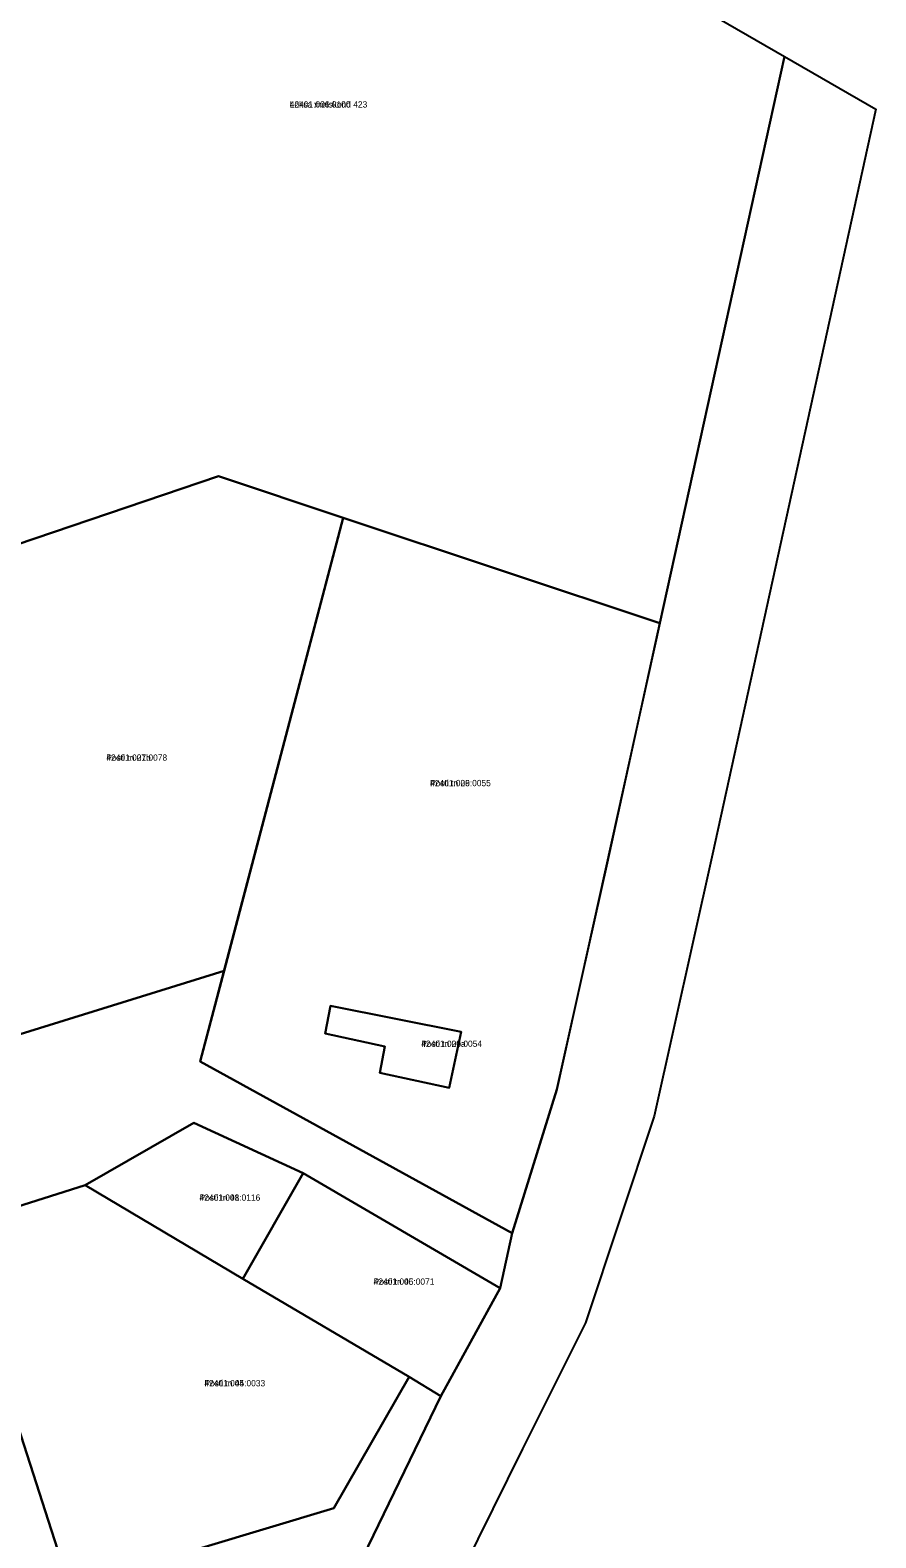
# Model space of a CAD drawing. Extents: x 595979 to 597983, y 6604231 to 6607350.
# Drawn here: x 597780.8 to 597982.6, y 6606558.1 to 6606917.7 of the extents above; entities that cross this region are included whole.
import ezdxf

# ---------------------------------------------------------------- set-up
doc = ezdxf.new("R2010")
doc.units = 0
for name, color, linetype in [('L_AADRESS', 7, 'Continuous'), ('PIIR', 7, 'Continuous'), ('TUNNUS', 7, 'Continuous')]:
    doc.layers.add(name, color=color, linetype=linetype)

msp = doc.modelspace()

# ---------------------------------------------------------------- linework, layer by layer
at = {"layer": 'PIIR'}
for points in [[(597960.77, 6606911.42), (597931.09, 6606776.25), (597855.49, 6606801.38), (597825.72, 6606811.32), (597742.46, 6606783.1), (597698.67, 6606769.19), (597711.53, 6606826.13), (597746.71, 6606988.38), (597756.25, 6607029.31)], [(597827.06, 6606693.36), (597776.08, 6606677.55), (597742.46, 6606783.1), (597825.72, 6606811.32), (597855.49, 6606801.38)], [(597821.36, 6606671.69), (597855.49, 6606801.38), (597931.09, 6606776.25), (597906.51, 6606665.03), (597895.79, 6606630.74)], [(597852.44, 6606684.98), (597883.61, 6606678.82), (597880.78, 6606665.43), (597864.21, 6606669.04), (597865.4, 6606675.28), (597851.19, 6606678.4)], [(597851.19, 6606678.4), (597865.4, 6606675.28), (597864.21, 6606669.04), (597880.78, 6606665.43), (597883.61, 6606678.82), (597852.44, 6606684.98)], [(597831.54, 6606619.92), (597793.92, 6606642.25), (597819.84, 6606657.09), (597845.95, 6606645.08)], [(597845.95, 6606645.08), (597892.93, 6606617.65), (597878.8, 6606591.86), (597871.24, 6606596.51), (597831.54, 6606619.92)], [(597762.54, 6606632.31), (597793.92, 6606642.25), (597831.54, 6606619.92), (597871.24, 6606596.51), (597853.26, 6606565.17), (597790.29, 6606546.25)], [(597716.73, 6606617.61), (597762.54, 6606632.31), (597790.29, 6606546.25), (597746.05, 6606532.03)]]:
    msp.add_lwpolyline(points, close=True, dxfattribs=at)
for points in [[(597852.82, 6606538.23), (597878.8, 6606591.86), (597892.93, 6606617.65), (597895.79, 6606630.74), (597906.51, 6606665.03), (597918.6, 6606719.12), (597931.09, 6606776.25), (597960.77, 6606911.42), (597982.61, 6606898.84), (597943.62, 6606721.19), (597929.69, 6606658.71), (597913.31, 6606609.35), (597898.31, 6606579.37), (597873.37, 6606529.02)], [(597776.08, 6606677.55), (597827.06, 6606693.36), (597821.36, 6606671.69), (597895.79, 6606630.74), (597892.93, 6606617.65), (597845.95, 6606645.08), (597819.84, 6606657.09), (597793.92, 6606642.25), (597762.54, 6606632.31)], [(597790.29, 6606546.25), (597853.26, 6606565.17), (597871.24, 6606596.51), (597878.8, 6606591.86), (597852.82, 6606538.23)]]:
    msp.add_lwpolyline(points, dxfattribs=at)

# ---------------------------------------------------------------- texts
at = {"layer": 'L_AADRESS'}
for s, p in [('Loksa metskond 423', (597842.74, 6606899.25)), ('Posti tn 27b', (597798.98, 6606743.45)), ('Posti tn 29', (597876.23, 6606737.38)), ('Posti tn 29a', (597874.12, 6606675.21)), ('Posti tn 48', (597821.21, 6606638.51)), ('Posti tn 46', (597862.76, 6606618.47)), ('Posti tn 44', (597822.38, 6606594.25))]:
    msp.add_text(s, height=1.5, dxfattribs=at).set_placement(p)
at = {"layer": 'TUNNUS'}
for s, p in [('42401:006:0100', (597842.74, 6606899.25)), ('42401:001:0078', (597798.98, 6606743.45)), ('42401:006:0055', (597876.23, 6606737.38)), ('42401:006:0054', (597874.12, 6606675.21)), ('42401:001:0116', (597821.21, 6606638.51)), ('42401:005:0071', (597862.76, 6606618.47)), ('42401:005:0033', (597822.38, 6606594.25))]:
    msp.add_text(s, height=1.5, dxfattribs=at).set_placement(p)

doc.saveas('drawing.dxf')
